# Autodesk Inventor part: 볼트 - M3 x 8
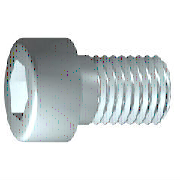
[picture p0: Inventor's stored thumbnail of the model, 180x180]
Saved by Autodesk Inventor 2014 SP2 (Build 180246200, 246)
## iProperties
IsCustomPart: 0
Created: 2012-02
Part Number: 볼트 - M3 x 8
Material: 스테인리스강
Description: 6각 소켓 머리 캡 나사
Document SubType Name: Modeling
Standard: ISO 4762
Designer: mduedu
Standard Revision: Fourth edition 2004-03-01
Standards Organization: ISO
Language: ko-KR
Size Designation: M3 x 8
Categories: <MemberInstance><Categories><Category DisplayName="조임쇠" InternalName="e4da775c-781d-43d5-af7c-5136215cf5a6" Mnemonic="FSTN"><Category DisplayName="볼트" InternalN
Density: 8.08 g/cm^3
Mass: 0.955869 g
Surface Area: 1.83001 cm^2
Volume: 0.118301 cm^3
Appearance: 반광택
Author: mduedu
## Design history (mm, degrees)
sketch "스케치1"
  geometry: L1 (-0.867, 0)-(8, 0); L2 (8, 0)-(8, 1.5); L3 (8, 1.5)-(1.25, 1.5); L4 (1.25, 1.5)-(0.943, 1.5); L5 (0.943, 1.5)-(0, 1.5); L6 (0, 1.5)-(0, 2.75); L7 (0, 2.75)-(-3, 2.75); L8 (-3, 2.75)-(-3, 1.443); L9 (-3, 1.443)-(-1.7, 1.443); L10 (-1.7, 1.443)-(-0.867, 0); L11 (-5.2, 0)-(10.2, 0) reference; L12 (0, -0.55)-(0, 3.3) reference; L13 (1.25, 1.5)-(0, 1.5)
  constraints: 22 end point, 6 parallel, 2 collinear, 2 perpendicular, 1 horizontal, 1 point on line
  dimensions: "d1" = 6.75 distance from line of L3.end L2 (= GEL); "d2" = 0.30683 distance of L4.end L3.end (computed from GAL); "d3" = 3 distance between parallel lines of L8 L6 (= KOH); "d4" = 1.3 distance of L8.end L9.end (= INTI); "d5" = 60 deg angle of L10 L1; "d6" = 3 diameter of L3 L1 (= GD); "d7" = 3 diameter of L5 L1 (= BDM); "d8" = 2.88675 diameter of L9 L1 (= 1.1547 x SW); "d9" = 5.5 diameter of L7 L1 (= KOD); "d26" = 8 distance between parallel lines of L12 L2 (= NLG)
revolve "본체" sketch "스케치1" stored, may be unused: angle "d10" = 90 deg
sketch "스케치2"
  geometry: L1 (0, -3.85)-(0, 3.85) reference; L2 (-3.85, 0)-(3.85, 0) reference; L3 (1.443, 0)-(0.722, -1.25); L4 (0.722, -1.25)-(-0.722, -1.25); L5 (-0.722, -1.25)-(-1.443, 0); L6 (-1.443, 0)-(-0.722, 1.25); L7 (-0.722, 1.25)-(0.722, 1.25); L8 (0.722, 1.25)-(1.443, 0); 2 further points
  constraints: 12 end point, 1 coincident, 1 horizontal alignment, 1 point on line, 12 other
extrude "슬롯" join sketch "스케치2" stored distance "d11" = 10; taper "d12" = 0 deg
workplane "Work Plane1"
fillet "Fillet2" dims "d30" = 0.1 (= R)
body "Solid1"
fillet "모깎기1" dims "d17" = 0.3 (= RR)
feature "스레드" dims "d13" = 6.75 (= GEL), "d14" = 0
chamfer "모따기1" distance "d15" = 0.30673 (= -0.5 x SPD + 0.5 x GD); stored, may be unused: second distance "d16" = 0.30673 (= GUL), angle "d27" = 45 deg
other parameters: "GD" = 3 [user parameter; used in 2 equation terms], "NLG" = 8 [user parameter; used in 1 equation term], "GEL" = 6.75 [user parameter; used in 2 equation terms], "KOD" = 5.5 [user parameter; used in 1 equation term], "KOH" = 3 [user parameter; used in 1 equation term], "INTI" = 1.3 [user parameter; used in 1 equation term], "GAL" = 0.30673 (= 0.61345 x PTC) [user parameter; used in 1 equation term], "GUL" = 0.30673 (= 0.61345 x PTC) [user parameter; used in 1 equation term], "BDM" = 3 (= NND) [user parameter; used in 1 equation term], "SW" = 2.5 [user parameter; used in 2 equation terms], "RR" = 0.3 [user parameter; used in 1 equation term], "SPD" = 2.38655 (= NND - 1.2269 x PTC) [user parameter; used in 1 equation term], "d19" = 0, "d28" = 0, "d29" = 0, "R" = 0.1 [user parameter; used in 1 equation term], "TOA" = 30 deg [user parameter], "GD1" = 2.38655 (= THREADDIA - 1.2269 x PTC) [user parameter], "THREADDIA" = 3 [user parameter; used in 1 equation term], "FAWI" = 45 deg [user parameter], "PTC" = 0.5 [user parameter; used in 5 equation terms], "NND" = 3 [user parameter; used in 2 equation terms], "E0" = 2.8875 (= 1.155 x SW) [user parameter]
